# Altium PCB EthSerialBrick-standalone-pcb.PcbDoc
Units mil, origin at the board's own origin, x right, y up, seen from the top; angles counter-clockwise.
Board outline 3550 x 3775 mil, 4 copper layers (Top Layer, Internal Plane 1, Internal Plane 2, Bottom Layer); 57 components, 52 nets, 310 pads, 15 vias.
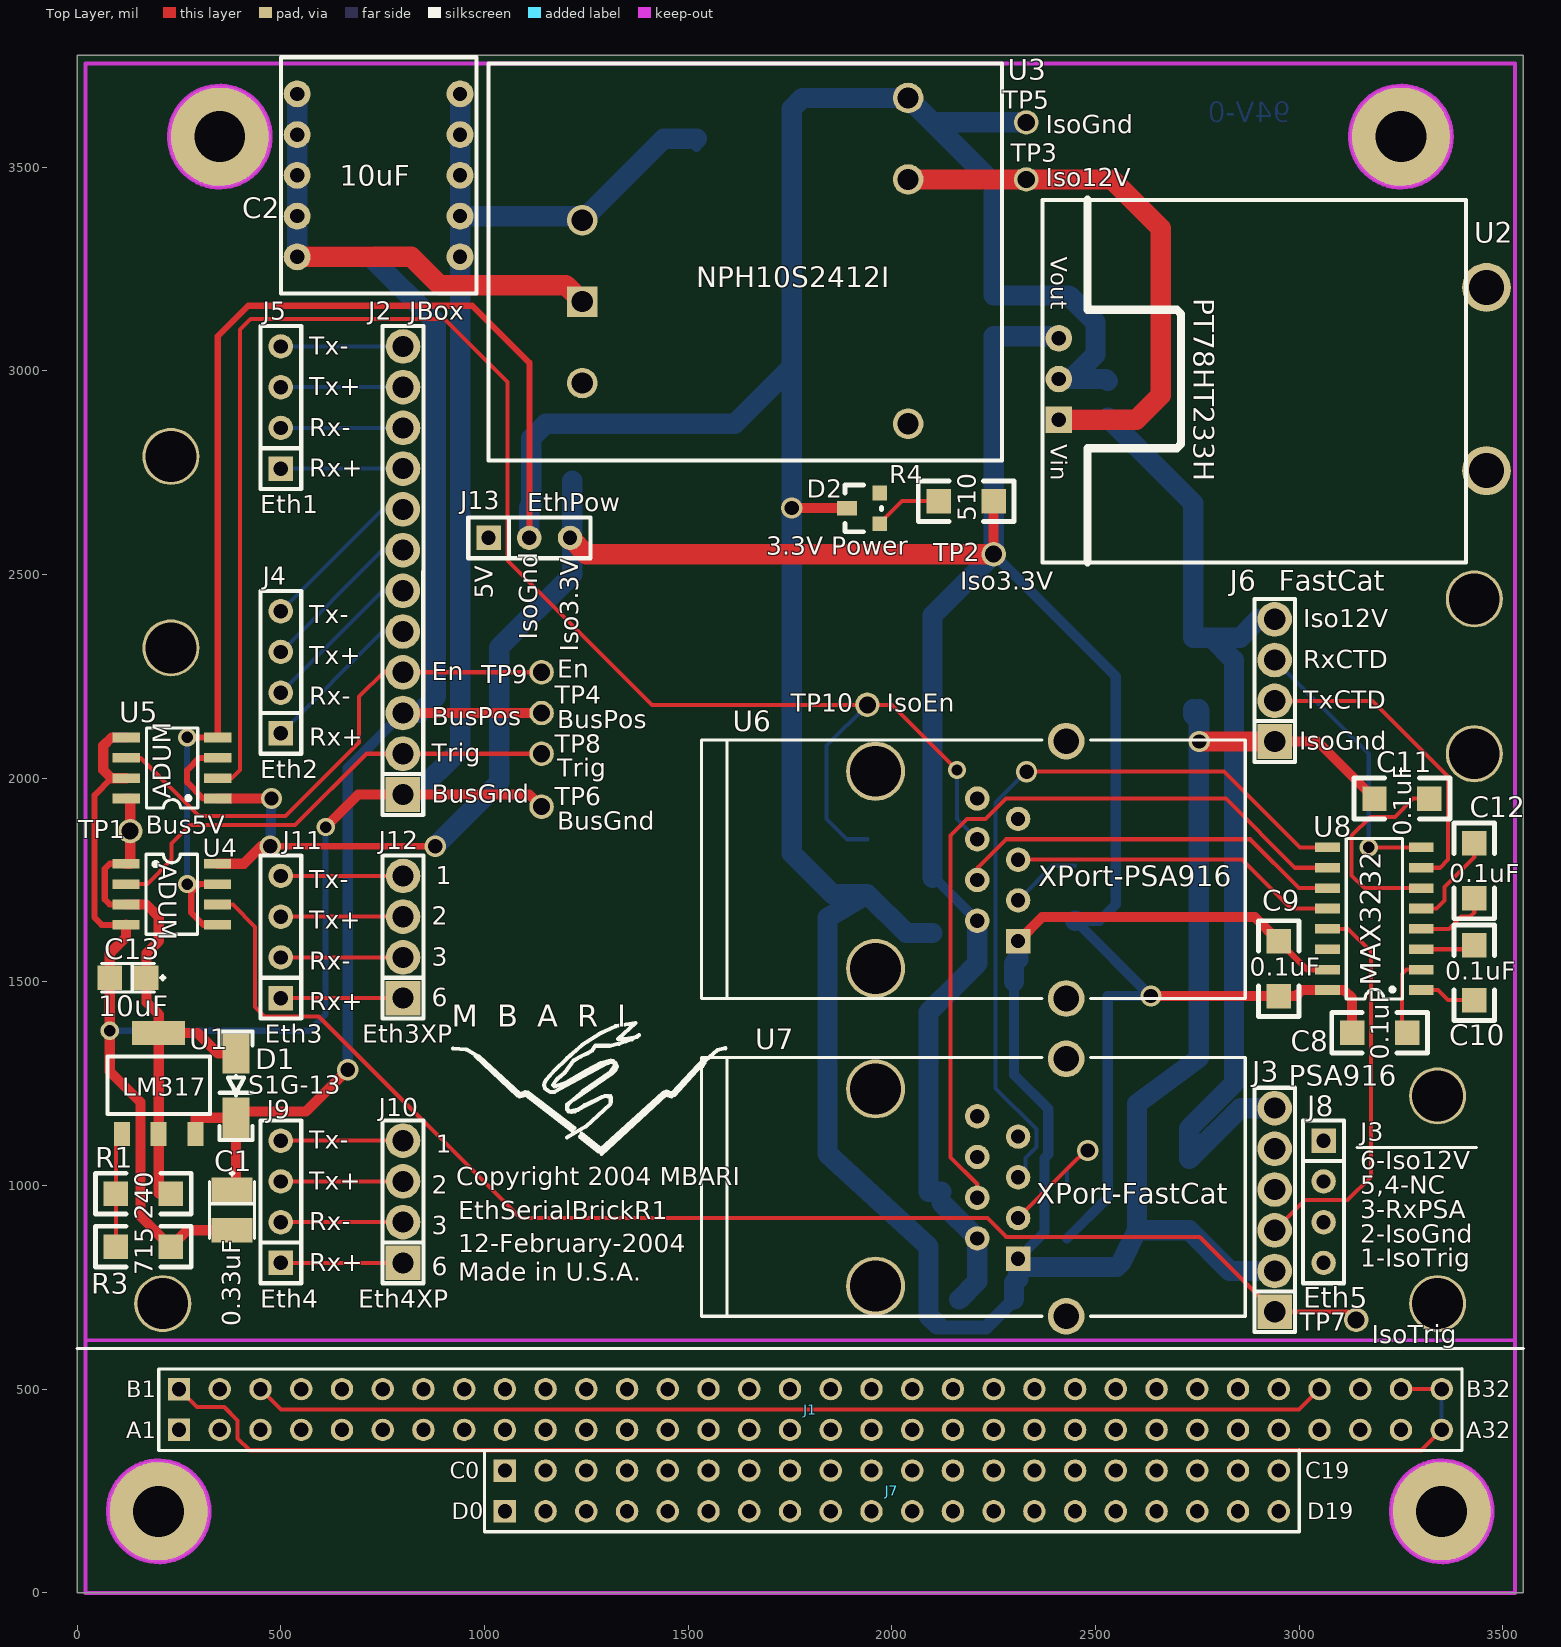
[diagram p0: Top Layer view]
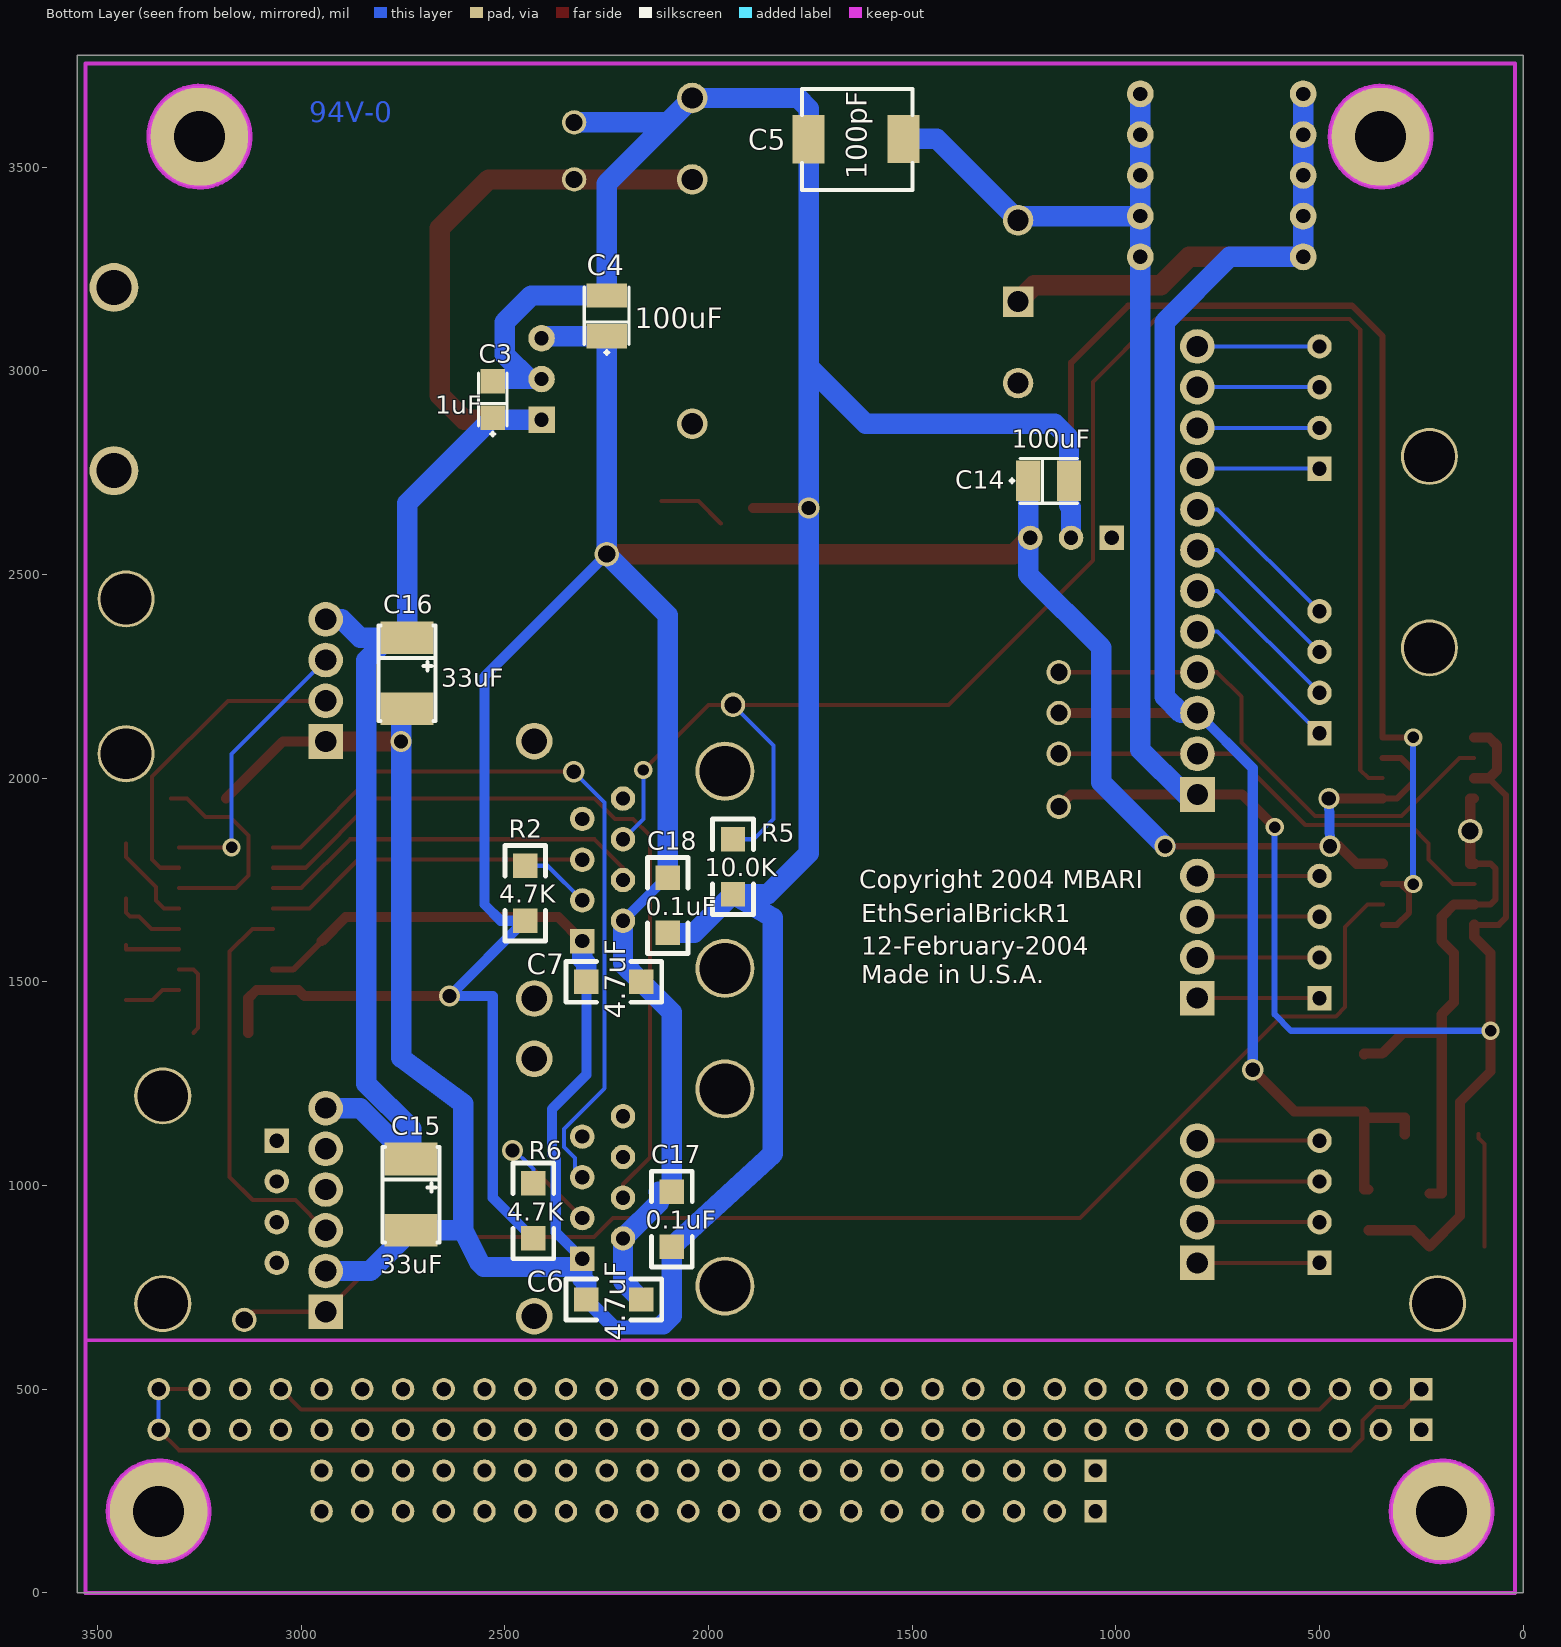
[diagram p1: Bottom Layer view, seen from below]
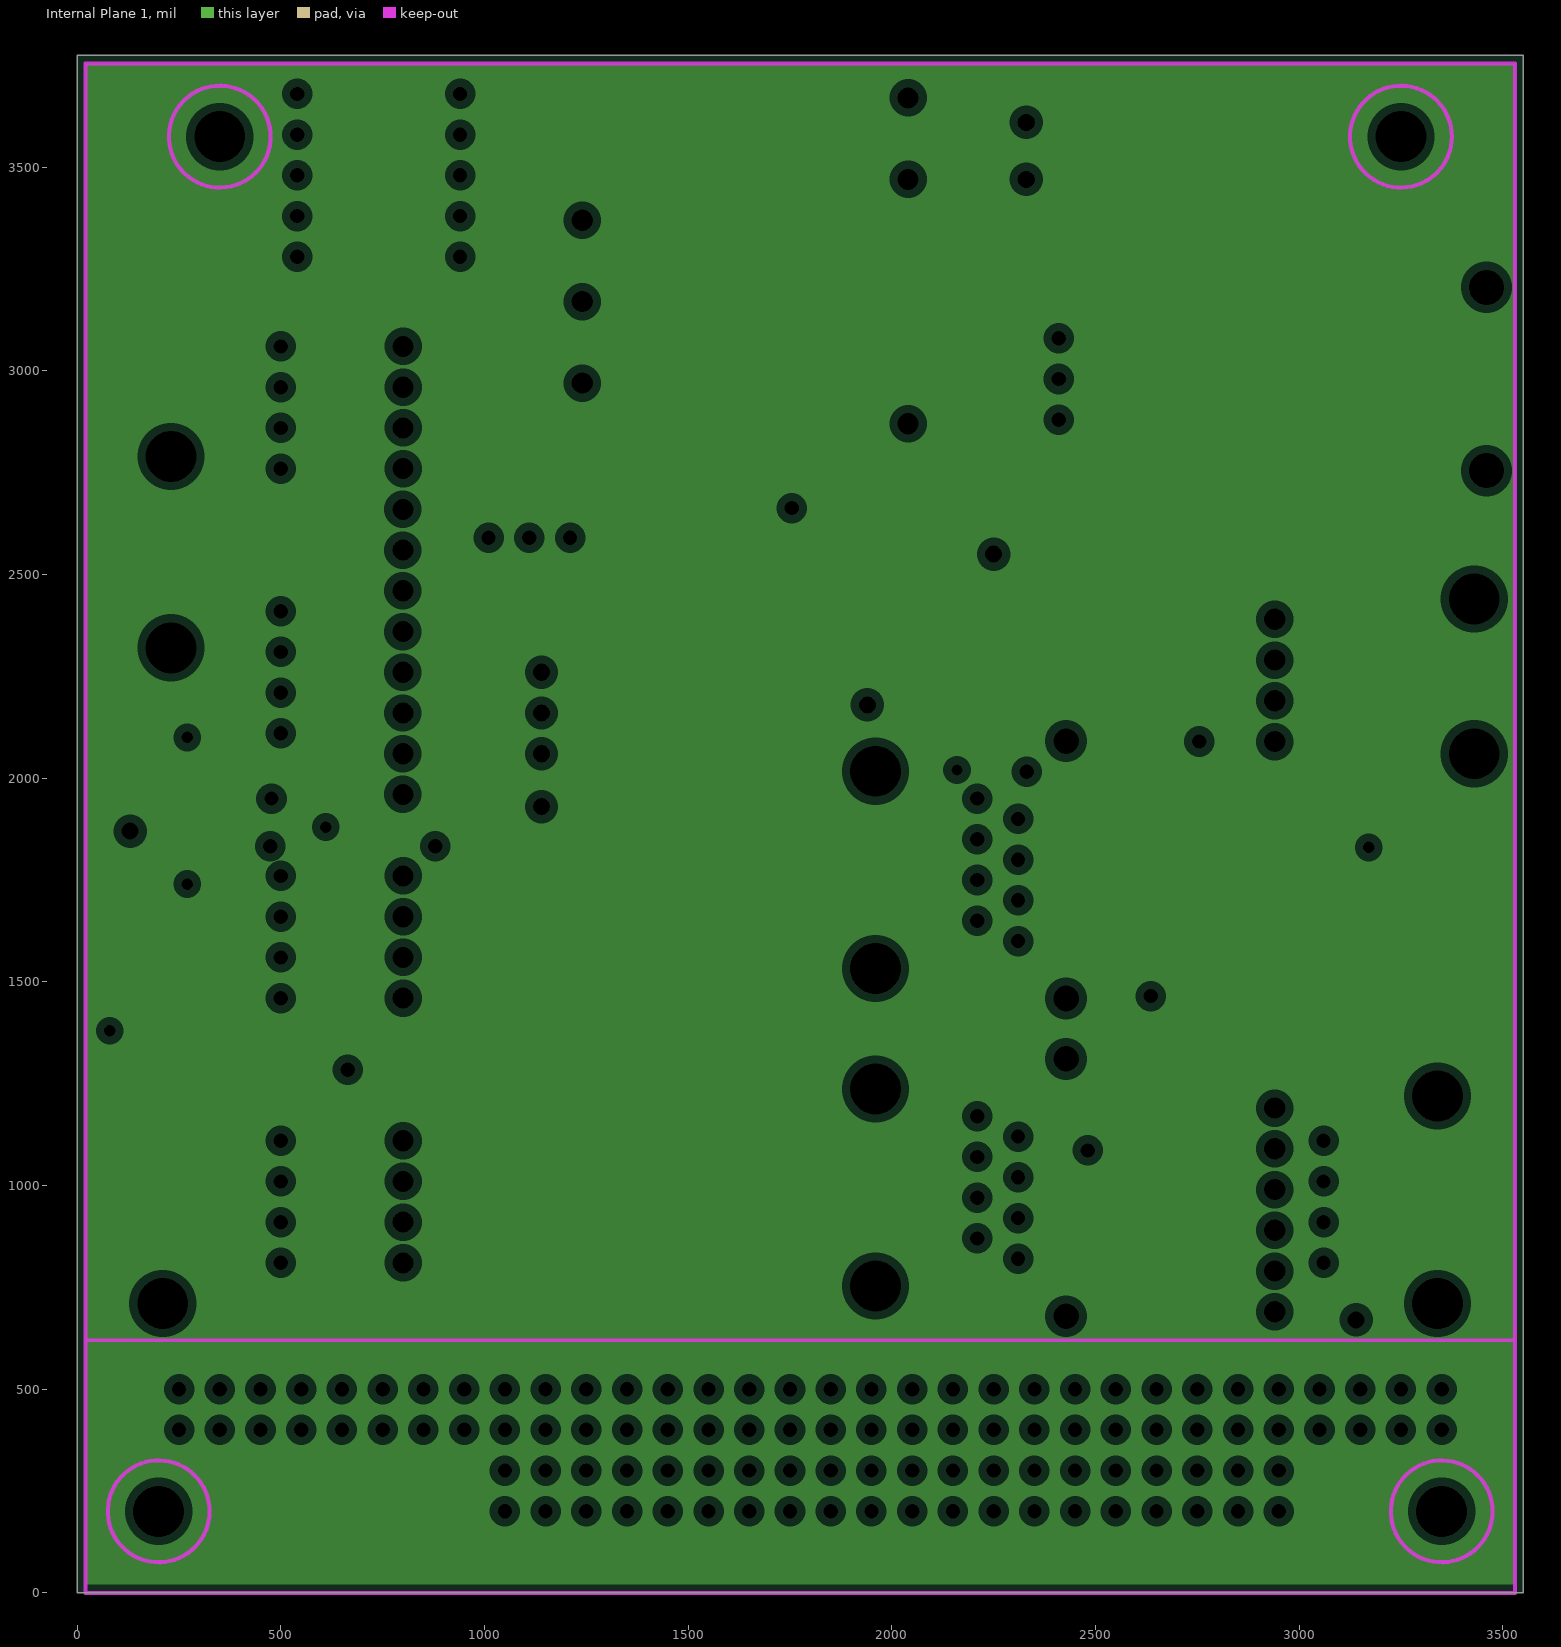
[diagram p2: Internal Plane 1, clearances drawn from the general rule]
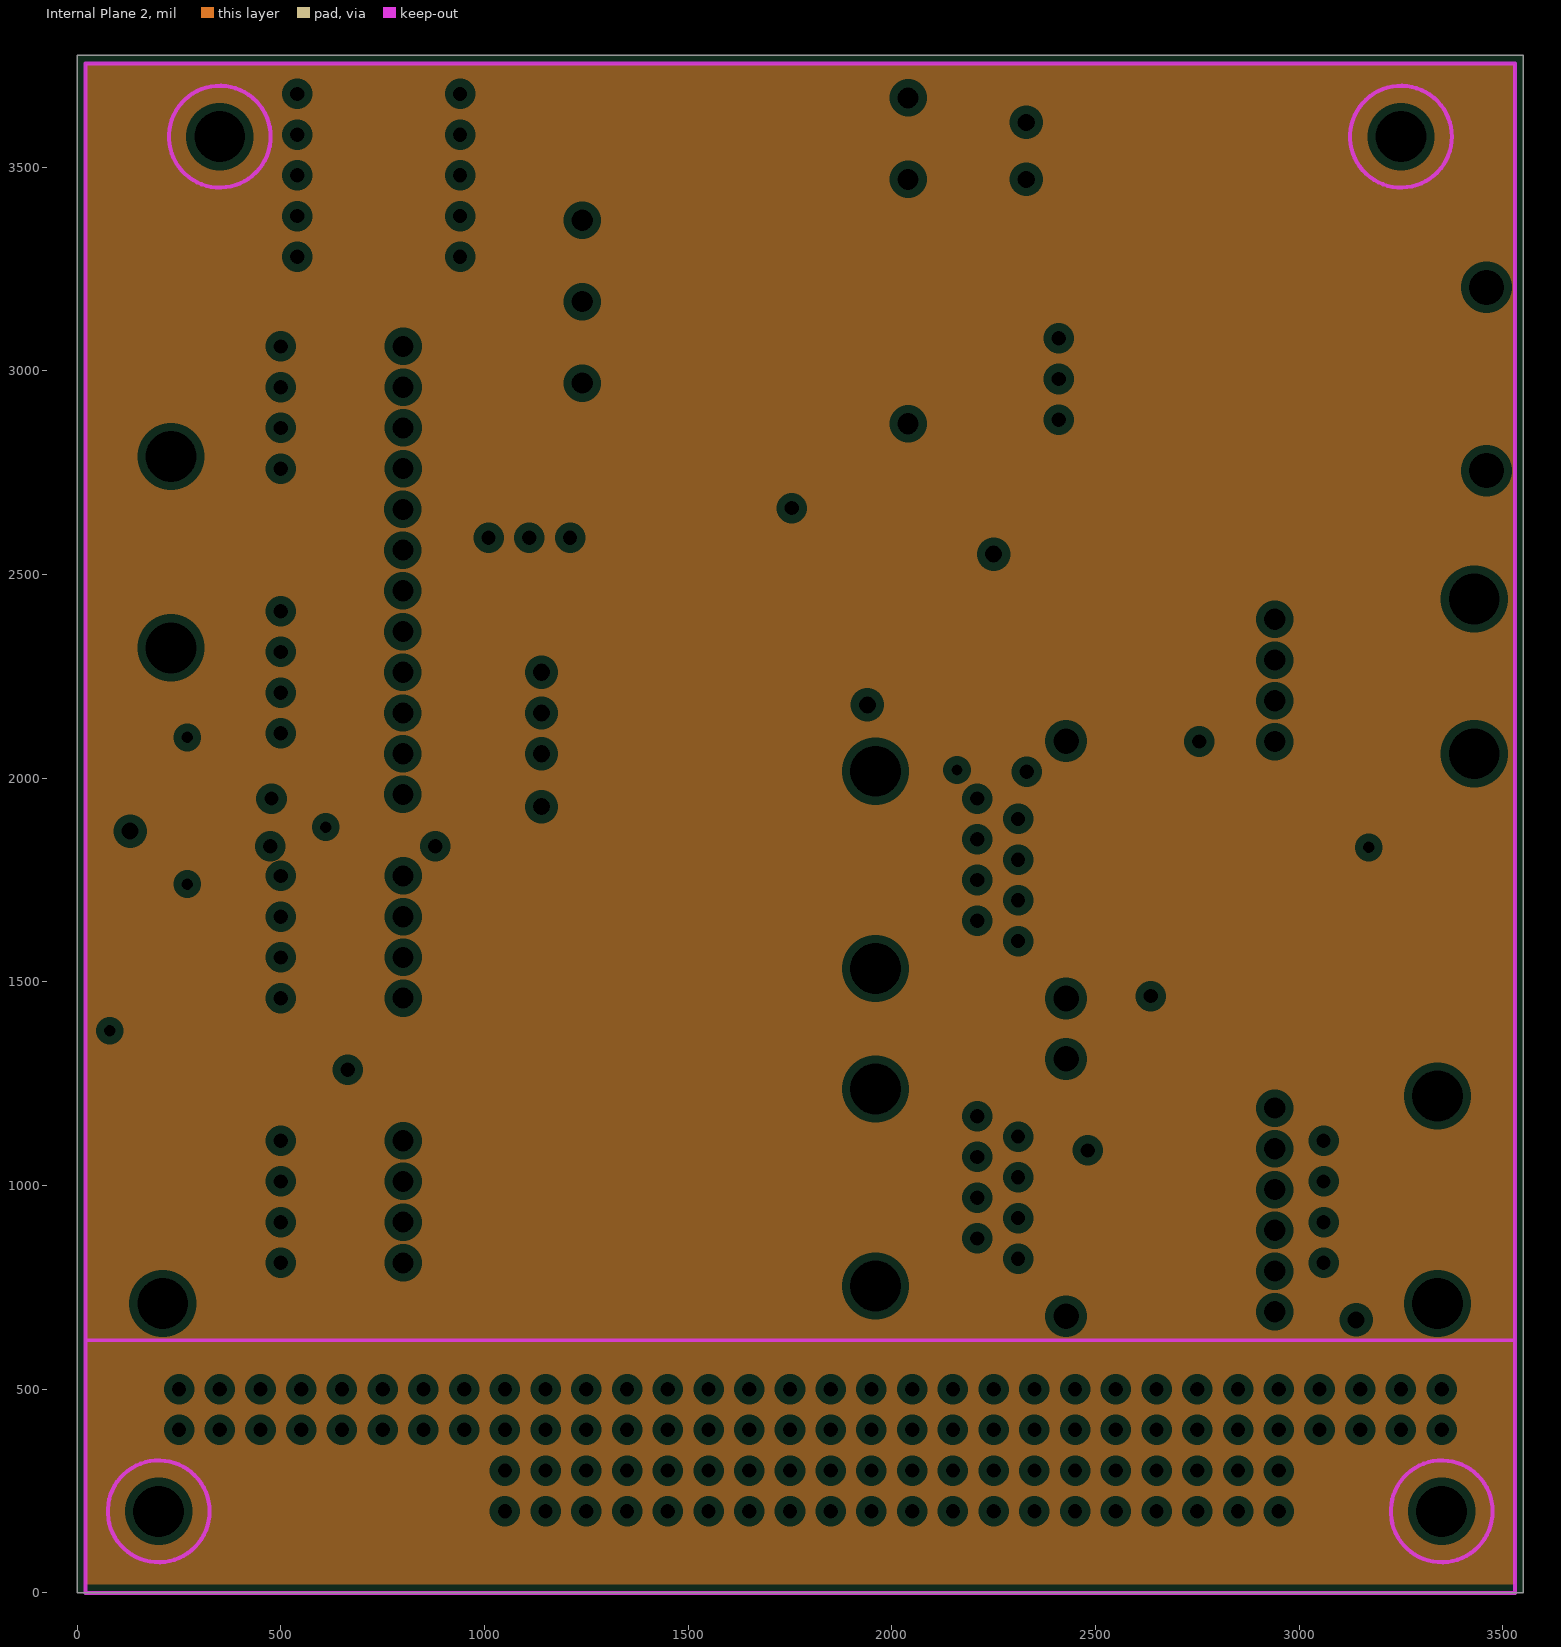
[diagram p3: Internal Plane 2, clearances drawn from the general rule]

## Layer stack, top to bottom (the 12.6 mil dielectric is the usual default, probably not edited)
Top Layer: signal copper 1.4
Dielectric: dielectric 12.6, FR-4, Dk 4.8
Internal Plane 1: plane copper 1.4
Dielectric: dielectric 12.6, FR-4, Dk 4.8
Internal Plane 2: plane copper 1.4
Dielectric: dielectric 12.6, FR-4, Dk 4.8
Bottom Layer: signal copper 1.4

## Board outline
0,0 0,3775 3550,3775 3550,0

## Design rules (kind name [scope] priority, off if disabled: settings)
Clearance Clearance_poly [InPolygon] p1: gap=16 // poly
Clearance [All] p2: gap=10
ComponentClearance [All] p1 off: gap=10 collisioncheckmode=0
FanoutControl Fanout_Small [(CompPinCount < 5)] p1: bgadir=Out bgaviamode=Centered fanoutstyle=Auto fanoutdirection=OutThenIn viagrid=1 // Fanout_Small (Default Rule)
FanoutControl Fanout_Default [All] p2: bgadir=Out bgaviamode=Centered fanoutstyle=Auto fanoutdirection=Alternating viagrid=1 // Fanout_Default (Default Rule)
FanoutControl Fanout_BGA [IsBGA] p4: bgadir=Out bgaviamode=Centered fanoutstyle=Auto fanoutdirection=Alternating viagrid=1 // Fanout_BGA (Default Rule)
FanoutControl Fanout_LCC [IsLCC] p5: bgadir=Out bgaviamode=Centered fanoutstyle=Auto fanoutdirection=Alternating viagrid=1 // Fanout_LCC (Default Rule)
HoleSize [All] p1: absolutevalues=TRUE maxlimit=152 minlimit=1 maxpercent=80.000 minpercent=20.000
MinimumAnnularRing [All] p1: minimumring=7.5
PlaneClearance [All] p1: clearance=20
PlaneConnect [All] p1: planeconnectstyle=Relief reliefexpansion=20 reliefentries=4 reliefconductorwidth=10 reliefairgap=10
PolygonConnect [All] p1: connectstyle=Relief reliefconductorwidth=10 reliefentries=4 polygonreliefangle="90 Angle"
RoutingLayers [All] p1: top layer=Horizontal bottom layer=Vertical
RoutingVias [All] p1: holewidth=28 width=45 viastyle="Through Hole" minholewidth=28 minwidth=43 maxholewidth=86 maxwidth=101
SolderMaskExpansion [All] p1: expansion=4
TestPointUsage [All] p1: valid=0 allowmultiple=FALSE
Testpoint [All] p1: side=15 testpointundercomponent=TRUE minsize=40 maxsize=100 preferedsize=60 minholesize=0 maxholesize=40 preferedholesize=32 testpointgrid=1 style=1023 order=1234567890
Width Width_power [InNetClass('Power')] p1: maxlimit=250 minlimit=10 preferedwidth=10 toplayer_prefwidth=25 bottomlayer_prefwidth=50 minimp=50.000000 maximp=50.000000 favimp=50.000000 // power width rule
Width [All] p2: maxlimit=250 minlimit=8 preferedwidth=12 toplayer_prefwidth=10 bottomlayer_prefwidth=10 minimp=50.000000 maximp=50.000000 favimp=50.000000
9 further rules are at their usual default settings.

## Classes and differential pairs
net class Power: BUS5V BUSGND BUSPOS ISO3.3V ISO12V ISOGND

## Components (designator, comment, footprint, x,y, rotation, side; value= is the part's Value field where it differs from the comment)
C1 "0.33uF" 3528POL 380,990 r270 top (schematic designator C13)
C2 "10uF" CAPSTICK-CS4-5 540,3280 r90 top
C3 "1uF" 3216POL 2530,2885 r90 bottom
C4 "100uF" 3528POL 2250,3085 r90 bottom
C5 "100pF" ECK 1514.92,3550 r0 bottom (schematic designator C11)
C6 "4.7uF" 1206 2165,720 r0 bottom (schematic designator C12)
C7 "4.7uF" 1206 2165,1500 r0 bottom (schematic designator C14)
C8 "0.1uF" 1206 3265,1375 r180 top (schematic designator C6)
C9 "0.1uF" 1206 2950,1465 r90 top (schematic designator C7)
C10 "0.1uF" 1206 3430,1455 r90 top (schematic designator C8)
C11 "0.1uF" 1206 3185,1950 r0 top (schematic designator C9)
C12 "0.1uF" 1206 3430,1705 r90 top (schematic designator C10)
C13 "10uF" 3216POL 170,1510 r180 top (schematic designator R4)
C14 "100uF" 3528POL 1215,2730 r180 bottom
C15 "33uF" 6032POL 2730,1065 r270 bottom
C16 "33uF" 6032POL 2740,2345 r270 bottom
C17 "0.1uF" 1206 2090,985 r270 bottom
C18 "0.1uF" 1206 2100,1755 r270 bottom
D1 "S1G-13" SMA 390,1245 r270 top (schematic designator D2)
D2 "3.3V Power" SOT-23 1970,2700 r90 top
J1 "PC104-AB" PC104-AB 250,400 r0 top locked (schematic designator J2)
J2 "JBox" SIP12 800,1960 r90 top (schematic designator J10)
J3 "PSA916" SIP6 2940,690 r90 top (schematic designator J11)
J4 "Eth2" SIP4#1 500,2110 r90 top locked (schematic designator J6)
J5 "Eth1" SIP4#1 500,2760 r90 top locked
J6 "FastCat" SIP4#2 2940,2090 r90 top (schematic designator J12)
J7 "PC104-CD" PC104-CD 1050,200 r0 top locked (schematic designator J3)
J8 "Eth5" SIP4#1 3060,1110 r270 top locked (schematic designator J9)
J9 "Eth4" SIP4#1 500,810 r90 top locked (schematic designator J8)
J10 "Eth4XP" SIP4#2 800,810 r90 top (schematic designator J13)
J11 "Eth3" SIP4#1 500,1460 r90 top locked (schematic designator J7)
J12 "Eth3XP" SIP4#2 800,1460 r90 top (schematic designator J14)
J13 "EthPow" SIP3 1010,2590 r0 top locked
R1 "240" 1206 230,980 r180 top (schematic designator R2)
R2 "4.7K" 1206 2450,1785 r270 bottom
R3 "715" 1206 230,850 r180 top
R4 "510" 1206 2250,2680 r180 top
R5 "10.0K" 1206 1940,1715 r90 bottom
R6 "4.7K" 1206 2430,1005 r270 bottom
TP1 "Bus5V" TP-PAD-35 130,1870 r0 top
TP2 "Iso3.3V" TP-PAD-35 2250,2550 r0 top
TP3 "Iso12V" TP-PAD-35 2330,3470 r0 top
TP4 "BusPos" TP-PAD-35 1140,2160 r0 top
TP5 "IsoGnd" TP-PAD-35 2330,3610 r0 top
TP6 "BusGnd" TP-PAD-35 1140,1930 r0 top
TP7 "IsoTrig" TP-PAD-35 3140,670 r90 top
TP8 "Trig" TP-PAD-35 1140,2060 r0 top
TP9 "En" TP-PAD-35 1140,2260 r90 top
TP10 "IsoEn" TP-PAD-35 1940,2180 r270 top
U1 "LM317EMP" SOT-223 200,1250 r0 top
U2 "PT78HT233H" PT78ST-HORIZ 2410,2980 r270 top (schematic designator U4)
U3 "NPH10S2412I" NPH10S 1240,3170 r180 top (schematic designator U9)
U4 "ADUM1100AR" SO-G8/D5 120,1790 r270 top (schematic designator U5)
U5 "ADUM1100AR" SO-G8/D5 345,1950 r90 top (schematic designator U6)
U6 "XPort-PSA916" XPORT 2310,1600 r0 top (schematic designator U3)
U7 "XPort-FastCat" XPORT 2310,820 r0 top
U8 "MAX3232" SOIC-16-0.15W 3300,1480 r90 top (schematic designator U2)

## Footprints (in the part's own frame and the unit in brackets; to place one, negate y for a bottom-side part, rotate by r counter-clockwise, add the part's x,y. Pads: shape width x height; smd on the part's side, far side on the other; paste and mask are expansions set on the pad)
1206 [mil]
  rect 60x60 smd: 1(0,0) 2(135,0)
  silkscreen extent -50,-50 185,50
3216POL [mil] "Polarized Cap EIA-3216-18, similiar to1206 footprint"
  rect 60x60 smd: 1(0,0) 2(90,0)
  silkscreen extent -45,-35 110,35
3528POL [mil] "Polarized chip capacitor EIA 3528-21"
  rect 60x100 smd: 1(0,0) 2(100,0)
  silkscreen extent -45,-55 120,55
6032POL [mil] "Polarized chip cap EIA 6032-28"
  rect 80x130 smd: 1(0,0) 2(175,0)
  silkscreen extent -30,-70 205,70
CAPSTICK-CS4-5 [mil]
  round 66 hole 35: 1(0,0) 1(100,0) 1(200,0) 1(300,0) 1(400,0) 2(0,-400) 2(100,-400) 2(200,-400) 2(300,-400) 2(400,-400)
  silkscreen extent -90,-440 490,40
ECK [mm]
  rect 2x3 smd: 1(0.15,-0.5) 2(6.075,-0.475)
  silkscreen extent -0.4,-3.6 6.5,2.7
NPH10S [mil]
  rect 75x75 hole 52: 1(0,0)
  round 75 hole 52: 2(0,-200) 3(-800,-500) 4(-800,-300) 5(0,200) 6(-800,300)
  silkscreen extent -1030,-585 230,390
PC104-AB [mil] "PC/104 A&B rails"
  rect 55x55 hole 35: A1(0,0) B1(0,100)
  round 55 hole 35: A2(100,0) A3(200,0) A4(300,0) A5(400,0) A6(500,0) A7(600,0) A8(700,0) A9(800,0) A10(900,0) A11(1000,0) A12(1100,0) A13(1200,0) A14(1300,0) A15(1400,0) A16(1500,0) A17(1600,0) A18(1700,0) A19(1800,0) A20(1900,0) A21(2000,0) A22(2100,0) A23(2200,0) A24(2300,0) A25(2400,0) A26(2500,0) A27(2600,0) A28(2700,0) A29(2800,0) A30(2900,0) A31(3000,0) A32(3100,0) B2(100,100) B3(200,100) B4(300,100) B5(400,100) B6(500,100) B7(600,100) B8(700,100) B9(800,100) B10(900,100) B11(1000,100) B12(1100,100) B13(1200,100) B14(1300,100) B15(1400,100) B16(1500,100) B17(1600,100) B18(1700,100) B19(1800,100) B20(1900,100) B21(2000,100) B22(2100,100) B23(2200,100) B24(2300,100) B25(2400,100) B26(2500,100) B27(2600,100) B28(2700,100) B29(2800,100) B30(2900,100) B31(3000,100) B32(3100,100)
  silkscreen extent -50,-50 3150,150
PC104-CD [mil] "PC/104 C&D rails"
  rect 55x55 hole 35: C0(0,100) D0(0,0)
  round 55 hole 35: C1(100,100) C2(200,100) C3(300,100) C4(400,100) C5(500,100) C6(600,100) C7(700,100) C8(800,100) C9(900,100) C10(1000,100) C11(1100,100) C12(1200,100) C13(1300,100) C14(1400,100) C15(1500,100) C16(1600,100) C17(1700,100) C18(1800,100) C19(1900,100) D1(100,0) D2(200,0) D3(300,0) D4(400,0) D5(500,0) D6(600,0) D7(700,0) D8(800,0) D9(900,0) D10(1000,0) D11(1100,0) D12(1200,0) D13(1300,0) D14(1400,0) D15(1500,0) D16(1600,0) D17(1700,0) D18(1800,0) D19(1900,0)
  silkscreen extent -50,-50 1950,150
PT78ST-HORIZ [mil]
  round 120 hole 86: 0(-225,1050) 0(225,1050)
  rect 65x65 hole 35: 1(100,0)
  round 65 hole 35: 2(0,0) 3(-100,0)
  silkscreen extent -440,-40 450,1000
SIP3 [mil]
  rect 60x60 hole 35: 1(0,0)
  round 60 hole 35: 2(100,0) 3(200,0)
  silkscreen extent -50,-50 250,50
SIP4#1 [mil]
  rect 60x60 hole 35: 1(0,0)
  round 60 hole 35: 2(100,0) 3(200,0) 4(300,0)
  silkscreen extent -50,-50 350,50
SIP4#2 [mil]
  rect 85x85 hole 52: 1(0,0)
  round 85 hole 52: 2(100,0) 3(200,0) 4(300,0)
  silkscreen extent -50,-50 350,50
SIP6 [mil]
  rect 85x85 hole 52: 1(0,0)
  round 85 hole 52: 2(100,0) 3(200,0) 4(300,0) 5(400,0) 6(500,0)
  silkscreen extent -50,-50 550,50
SIP12 [mil] "12 position SIP"
  rect 85x85 hole 52: 1(0,0.38)
  round 85 hole 52: 2(100,0.38) 3(200,0.38) 4(300,0.38) 5(400,0.38) 6(500,0.38) 7(600,0.38) 8(700,0.38) 9(800,0) 10(900,0) 11(1000,0) 12(1100,0)
  silkscreen extent -50,-50 1150,50
SMA [mm] "SMA Diode"
  rect 2.5x1.7 smd: 1(-2,0) 2(2,0)
  silkscreen extent -3.38,-1.02 3.38,1.02
SO-G8/D5 [mm]
  rect 0.6x1.7 smd: 1(0,0) 2(1.27,0) 3(2.54,0) 4(3.81,0) 5(3.81,5.7) 6(2.54,5.7) 7(1.27,5.7) 8(0,5.7)
  silkscreen extent -0.59,1.25 4.41,4.45
SOIC-16-0.15W [mm] "SOIC-16 0.15\"Wide 1.27mm Pitch"
  rect 0.6x1.55 smd: 1(0,0) 2(1.27,0) 3(2.54,0) 4(3.81,0) 5(5.08,0) 6(6.35,0) 7(7.62,0) 8(8.89,0) 9(8.89,5.85) 10(7.62,5.85) 11(6.35,5.85) 12(5.08,5.85) 13(3.81,5.85) 14(2.54,5.85) 15(1.27,5.85) 16(0,5.85)
  silkscreen extent -0.55,1.18 9.44,4.67
SOT-23 [mil]
  rect 36x36 smd: 1(0,0) 2(-75,0)
  rect 36x50 smd: 3(-37,80)
  silkscreen extent -95,-5 20,85
SOT-223 [mm] "4 lead SMD NS:MP04A"
  rect 1x1.5 smd: 1(-2.3,-3.15) 2(0,-3.15) 3(2.3,-3.15)
  rect 3.3x1.5 smd: 4(0,3.15)
  silkscreen extent -3.2,-1.9 3.2,1.7
TP-PAD-35 [mil] "TestPoint 35mil"
  round 60 hole 42: 0(0,0)
XPORT [mil]
  round 145 hole 125: 0(-350,-67) 0(-350,417)
  rect 60x60 hole 35: 1(0,0)
  round 60 hole 35: 2(-100,50) 3(0,100) 4(-100,150) 5(0,200) 6(-100,250) 7(0,300) 8(-100,350)
  round 90 hole 63: 9(118,-141) 10(118,491)
  silkscreen extent -777,-141 558,494

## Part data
C1 C3 C4 C13 C14 C15 C16: library part "CAPACITOR POL", "Capacitor"
C2 C6 C7 C8 C9 C10 C11 C12 C17 C18: library part CAPACITOR, "Capacitor"
C5: library part Cap, "Capacitor"
D1: library part DIODE_S, "Diode"
D2: library part LED, "LED"
J1: "PC/104 A&B rails"
J2: library part CON12, "Connector 12 pin"
J3: library part CON6, "Connector"
J4 J5 J8 J9 J10 J11 J12: library part CON4, "Connector 4 pin"
J6: library part CON4, "Connector"
J7: "PC/104 C&D rails"
J13: library part CON3, "Connector"
R1 R2 R3 R4 R5 R6: library part RESISTOR, "Resistor"
TP1 TP2 TP3 TP4 TP5 TP6 TP7 TP8 TP9 TP10: library part "TP PIN", "Pad Pin for testpoints"
U1: library part LM317, "Regulator"
U2: library part PT78STXXX, "Power Trends Switching Reg"
U3: library part NPH10S, "DC->DC Isol Converter 10W"
U4 U5: "Digital Isolator"
U6 U7: library part XPORT, "Serial to Ethernet Converter"
U8: library part MAX232, "MAX232 Communications Chip"

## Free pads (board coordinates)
  round 250 hole 125: 0(200,200) 0(350,3575) 0(3250,3575) 0(3350,200)
  round 140 hole 125: 0(210,710) 0(230,2320) 0(230,2790) 0(3340,710) 0(3340,1220) 0(3430,2060) 0(3430,2440)

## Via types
v1: diameter 52, hole 35, Top Layer to Bottom Layer, 9 vias
v2: diameter 45, hole 28, Top Layer to Bottom Layer, 6 vias

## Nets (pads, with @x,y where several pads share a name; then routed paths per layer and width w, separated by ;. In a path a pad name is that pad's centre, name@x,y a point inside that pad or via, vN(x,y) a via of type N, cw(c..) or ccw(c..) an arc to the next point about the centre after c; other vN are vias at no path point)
104+5V: J1.B3 J1.B29 | length 2641.4
  Top Layer w10: J1.B3 500,450 3000,450 J1.B29
104GND: J1.A32 J1.B1 J1.B31 J1.B32 | length 3408.6
  Top Layer w10: J1.B1 294,456 361,456 394,423 394,379 423,350 3300,350 J1.A32 ; J1.B31 J1.B32
  Bottom Layer w10: J1.A32 J1.B32
BUS5V: C13.1 D1.1 R1.1 TP1.0 U1.2 U1.4 U4.1 U4.3 U5.8 | length 1409.6
  Top Layer w15: U4.3 80,1690 67.5,1702.5 67.5,1777.5 80,1790 U4.1
  Top Layer w25: U4.3 170,1690 200,1660 200,1600 170,1570 C13.1 170,1450 200,1420 U1.4 ; U4.1 130,1790 TP1.0 130,1950 U5.8 ; R1.1 200,980 U1.2 U1.4 ; D1.1@390,1322 D1.1 346.26,1323.74 295.98,1374.02 U1.4
BUSGND: C1.2 C2.2 C5.1 C13.2 J2.1 R3.1 TP6.0 U3.2 U4.4 U5.5 U5.7 | length 5771.5
  Top Layer w15: U4.4 60,1640 42.5,1657.5 42.5,1958.5 84,2000 U5.7
  Top Layer w25: U4.4 120,1610 80,1570 C13.2 80,1280 155,1205 155,925 R3.1 270,890 299,890 C1.2 ; U5.7 84,2000 64,2020 64,2080 84,2100 U5.5 ; v2(610,1880) 690,1960 J2.1 1110,1960 TP6.0
  Bottom Layer w15: v2(80,1380) 570,1380 610,1420 v2(610,1880)
  Bottom Layer w25: C5.1@1520.83,3550 C5.1
  Bottom Layer w50: J2.1 830,1960 940,2070 940,3280 C2.2@940,3380 ; C2.2@940,3680 940,3580 940,3480 C2.2@940,3380 ; C5.1 1439.69,3569.69 U3.2 1230,3380 C2.2@940,3380
BUSPOS: C1.1 C2.1 D1.2 J2.3 TP4.0 U1.3 U3.1 | length 4499.3
  Top Layer w25: U1.3 290.55,1166.26 D1.2 ; C1.1 390,990 D1.2 ; v1(664,1284) 562,1182 390,1182 D1.2 ; J2.3 TP4.0
  Top Layer w50: C2.1@540,3280 820,3280 890,3210 1200,3210 U3.1
  Bottom Layer w25: v1(664,1284) 664,2024.38 J2.3
  Bottom Layer w50: C2.1@540,3680 540,3580 540,3480 540,3380 540,3280 720,3280 880,3120 880,2200 840,2160 J2.3
EN: J2.4 TP9.0 U5.6 | length 1290.5
  Top Layer w10: U5.6 156,2050 299,1907 511,1907 692,2088 692,2200 752,2260 J2.4 TP9.0
ISO3.3V: C4.1 C6.1 C7.1 C8.2 C9.1 C14.1 C17.1 C18.1 J13.3 R2.2 R4.1 R6.2 TP2.0 U2.3 U4.8 U5.1 U5.3 U6.2 U7.2 U8.16 | length 8722.1
  Top Layer w15: U5.1 310,1950 270,1990 270,2020 300,2050 U5.3 ; v1(474,1833) v1(879,1833)
  Top Layer w25: U4.8 409,1790 452,1833 v1(474,1833) ; U5.1 v1(477,1950) ; TP2.0 R4.1 ; v1(2636,1465) C9.1 2992,1465 3007,1480 U8.16 3110,1480 3130,1460 C8.2
  Top Layer w50: J13.3 1250,2550 TP2.0
  Bottom Layer w25: v1(474,1833) v1(477,1950) ; C18.1 2105,1755 U6.2 ; 2122,958 2122,985 ; TP2.0 2503,2297 2550,2250 2550,1690 2510,1650 R2.2 ; R6.2 2530,970 2530,1465 v1(2636,1465) R2.2@2451,1650
  Bottom Layer w50: v1(879,1833) 1036,1990 1036,2321 1215,2500 J13.3@1215,2590 ; J13.3 J13.3@1215,2590 ; C14.1 J13.3@1215,2590 ; C18.1 2100,2400 TP2.0 C4.1 2405,3085 U2.3 U2.3@2400,3080 ; 2122,958 U7.2 2210,765 C6.1 ; 2122,985 C17.1 2090,1425 C7.1 2210,1545 U6.2 ; R2.2 R2.2@2451,1650
ISO12V: C3.1 C15.1 C16.1 J3.6 J6.4 TP3.0 U2.1 U3.4 | length 3977.4
  Top Layer w50: U3.4 TP3.0 2540,3470 2660,3350 2660,2940 2600,2880 U2.1
  Bottom Layer w50: U2.1 2525,2880 C3.1 2740,2675 C16.1 ; J3.6 2855,1190 C15.1 2730,1140 2840,1250 2840,2290 2785,2345 C16.1 ; J6.4 2900,2390 2855,2345 C16.1
ISOEN: R5.2 TP10.0 U5.2 U6.6 | length 4263
  Top Layer w10: U5.2 380,2000 400,2020 400,3101 426,3127 902,3127 1056,2973 1056,2535 1411,2180 TP10.0 2000,2180 v2(2160,2020)
  Bottom Layer w10: R5.2 1890,1850 1840,1900 1840,2080 TP10.0 ; v2(2160,2020) 2160,1900 U6.6
ISOGND: C3.2 C4.2 C5.2 C6.2 C7.2 C9.2 C11.1 C14.2 C15.2 C16.2 C17.2 C18.2 D2.3 J3.2 J6.1 J13.2 R5.1 TP5.0 U2.2 U3.3 U4.5 U4.7 U5.4 U6.1 U7.1 U8.15 | length 14019.7
  Top Layer w15: v2(270,1740) U4.7 300,1740 280,1720 280,1670 310,1640 U4.5 ; v2(270,2100) U5.4 345,3085 420,3160 970,3160 1110,3020 J13.2 ; C9.2 3020,1530 U8.15
  Top Layer w25: v1@1754.09,2663 v1@1768,2663 ; v1(1754.09,2663.09) 1767.91,2663.09 v1@1768,2663 ; D2.3 1809,2663 v1@1768,2663 ; U6.1 2369,1659 2891,1659 C9.2 ; J6.1 3045,2090 C11.1
  Top Layer w50: v1(2755,2090) J6.1
  Bottom Layer w15: v2(270,1740) v2(270,2100)
  Bottom Layer w25: C7.2 2300,1272 2384,1188 2384,1076 2375,1067 2375,885 2345.5,855.5 U7.1
  Bottom Layer w35: 2111,659 2118.5,651.5 2231.5,651.5 C6.2
  Bottom Layer w50: J13.2 1110,2665 1115,2670 C14.2 1115,2835 1150,2870 1614.09,2870 1754.09,3010 ; C18.2 2035,1620 R5.1 ; 2111,659 2090,680 C17.2 1842,1078 1842,1657 R5.1 ; C6.2 2300,761 2310,771 U7.1 2330,800 2552,800 2563,811 2602,890 ; C7.2 2300,1545 2310,1555 U6.1 ; TP5.0 2100,3610 U3.3 ; U2.2 2525,2980 C3.2 ; U2.2@2440,2980 2500,3040 2500,3120 2435,3185 C4.2 2250,3460 U3.3 ; C16.2 2740,2155 C16.2@2755,2140 ; C16.2@2754,2170 2754,1416 2754,1313 2602,1201 2602,890 ; v1(2755,2090) C16.2@2755,2165 ; J3.2 2830,790 C15.2 2602,890 ; 1754.09,3010 C5.2 1754.09,3644.09 1780,3670 U3.3 ; 1754.09,3010 v1(1754.09,2663.09) 1754.09,1815.91 1855,1715 R5.1
ISOTRIG: J3.1 TP7.0 U4.6 | length 3333.5
  Top Layer w10: U4.6 382,1690 437,1635 437,1438 460,1415 593,1415 1088,920 2235,920 2281,874 2756,874 J3.1 3120,690 TP7.0
NetC8_1: C8.1 U8.2 | length 200.5
  Top Layer w10: C8.1 3253,1387 3253,1519 3264,1530 U8.2
NetC10_1: C10.1 U8.1 | length 140.4
  Top Layer w10: U8.1 3340.51,1480 3365.51,1455 C10.1
NetC10_2: C10.2 U8.3 | length 140
  Top Layer w10: U8.3 3430,1580 C10.2
NetC11_2: C11.2 U8.6 | length 510.5
  Top Layer w10: U8.6 3160,1730 3129,1761 3129,1839 3129,1859 3175,1905 3195,1905 3235,1905 3280,1950 C11.2
NetC12_1: C12.1 U8.4 | length 181.6
  Top Layer w10: U8.4 3368,1630 3398,1660 3420,1660 3430,1670 C12.1
NetC12_2: 
NetC12_2: C12.2 U8.5 | length 235.5
  Top Layer w10: U8.5 3337,1680 3357,1700 3357,1733 3430,1806 C12.2
NetD2_2: D2.2 R4.2 | length 167.8
  Top Layer w10: D2.2 2025,2680 R4.2
NetJ2_5: J2.5 J4.1 | length 403.2
  Bottom Layer w10: J4.1 750,2360 J2.5
NetJ2_6: J2.6 J4.2 | length 403.2
  Bottom Layer w10: J4.2 750,2460 J2.6
NetJ2_7: J2.7 J4.3 | length 403.2
  Bottom Layer w10: J4.3 750,2560 J2.7
NetJ2_8: J2.8 J4.4 | length 403.2
  Bottom Layer w10: J4.4 750,2660 J2.8
NetJ2_9: J2.9 J5.1 | length 300
  Bottom Layer w10: J5.1 J2.9
NetJ2_10: J2.10 J5.2 | length 300
  Bottom Layer w10: J5.2 J2.10
NetJ2_11: J2.11 J5.3 | length 300
  Bottom Layer w10: J5.3 J2.11
NetJ2_12: J2.12 J5.4 | length 300
  Bottom Layer w10: J5.4 J2.12
NetJ9_1: J9.1 J10.1 | length 300
  Top Layer w10: J9.1 J10.1
NetJ9_2: J9.2 J10.2 | length 300
  Top Layer w10: J9.2 J10.2
NetJ9_3: J9.3 J10.3 | length 300
  Top Layer w10: J9.3 J10.3
NetJ9_4: J9.4 J10.4 | length 300
  Top Layer w10: J9.4 J10.4
NetJ11_1: J11.1 J12.1 | length 300
  Top Layer w10: J11.1 J12.1
NetJ11_2: 
NetJ11_2: J11.2 J12.2 | length 300
  Top Layer w10: J11.2 J12.2
NetJ11_3: 
NetJ11_3: J11.3 J12.3 | length 300
  Top Layer w10: J11.3 J12.3
NetJ11_4: J11.4 J12.4 | length 300
  Top Layer w10: J11.4 J12.4
NetJ12_1: 
NetJ12_2: 
NetJ12_3: 
NetR1_2: R1.2 R3.2 U1.1 | length 282
  Top Layer w10: R3.2 R1.2 95,1101.55 109.45,1116 U1.1
NetR2_1: R2.1 U6.3 | length 175.2
  Bottom Layer w10: U6.3 2395,1785 R2.1
NetR6_1: R6.1 U7.3 | length 342.3
  Top Layer w10: U7.3 2456,1066 v1(2481,1086)
  Bottom Layer w10: R6.1 2430,1040 2456,1066 v1(2481,1086)
NetU6_4: U6.4 U8.11 | length 968.4
  Top Layer w10: U6.4 2210,1780 2280,1850 2880,1850 3000,1730 U8.11
NetU6_5: U6.5 U8.12 | length 809.4
  Top Layer w10: U6.5 2860,1800 2980,1680 U8.12
NetU7_4: U7.4 U8.10 | length 1950.1
  Top Layer w10: U7.4 2210,1003 2144,1069 2144,1859 2185,1900 2230,1900 2280,1950 2820,1950 2990,1780 U8.10
NetU7_5: U7.5 U8.9 | length 1913.8
  Top Layer w10: v1(2331,2016) 2816,2016 3002,1830 U8.9
  Bottom Layer w10: U7.5 2328,1020 2328,1068 2355,1095 2355,1138.64 2255,1238.64 2255,1940 v1(2331,2016)
RX1: J3.3 U8.13 | length 972.8
  Top Layer w10: J3.3 3014,964 3119,964 3176,1021 3176,1574 3120,1630 U8.13
RX2: J6.3 U8.8 | length 683.7
  Top Layer w10: v2@3172,1830 U8.8
  Bottom Layer w10: J6.3 3171,2059 v2(3171,1830)
TRIG: J2.2 TP8.0 U4.2 | length 1176
  Top Layer w10: U4.2 172,1740 232,1800 232,1840 277,1885 535,1885 710,2060 J2.2 TP8.0
TX1: U8.14
TX2: J6.2 U8.7 | length 781.2
  Top Layer w10: J6.2 3179.79,2190 3366,2003.79 3366,1800 3346,1780 U8.7
pads on no net: D2.1 J1.A1 J1.A2 J1.A3 J1.A4 J1.A5 J1.A6 J1.A7 J1.A8 J1.A9 J1.A10 J1.A11 J1.A12 J1.A13 J1.A14 J1.A15 J1.A16 J1.A17 J1.A18 J1.A19 J1.A20 J1.A21 J1.A22 J1.A23 J1.A24 J1.A25 J1.A26 J1.A27 J1.A28 J1.A29 J1.A30 J1.A31 J1.B2 J1.B4 J1.B5 J1.B6 J1.B7 J1.B8 J1.B9 J1.B10 J1.B11 J1.B12 J1.B13 J1.B14 J1.B15 J1.B16 J1.B17 J1.B18 J1.B19 J1.B20 J1.B21 J1.B22 J1.B23 J1.B24 J1.B25 J1.B26 J1.B27 J1.B28 J1.B30 J3.4 J3.5 J7.C0 J7.C1 J7.C2 J7.C3 J7.C4 J7.C5 J7.C6 J7.C7 J7.C8 J7.C9 J7.C10 J7.C11 J7.C12 J7.C13 J7.C14 J7.C15 J7.C16 J7.C17 J7.C18 J7.C19 J7.D0 J7.D1 J7.D2 J7.D3 J7.D4 J7.D5 J7.D6 J7.D7 J7.D8 J7.D9 J7.D10 J7.D11 J7.D12 J7.D13 J7.D14 J7.D15 J7.D16 J7.D17 J7.D18 J7.D19 J8.1 J8.2 J8.3 J8.4 J13.1 U2.0 U3.5 U3.6 U6.0 U6.7 U6.8 U6.9 U6.10 U7.0 U7.6 U7.7 U7.8 U7.9 U7.10

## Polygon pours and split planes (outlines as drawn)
no net on Internal Plane 1 (split plane): 20.01,20.01 20.01,3754.98 3529.98,3754.98 3529.98,20.01
no net on Internal Plane 2 (split plane): 20.01,20.01 20.01,3754.98 3529.98,3754.98 3529.98,20.01

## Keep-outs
Keep-Out Layer:
  circle w10: c200,200 r125
  circle w10: c350,3575 r125
  circle w10: c3250,3575 r125
  circle w10: c3350,200 r125
  lines w8: 20,620 3530,620
  lines w10: 20,0 3530,0 3530,3755 20,3755 20,0
  text ".GKO" at 15240,-540 h90

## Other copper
Top Layer:
  text ".GTL" at 15240,-540 h90
Bottom Layer:
  text "94V-0" at 2980,3610 h50
  text ".GBL" at 15240,-540 h90

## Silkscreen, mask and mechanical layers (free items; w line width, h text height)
Top Overlay:
  lines w8: 0,600 3550,600 ; 3142,1092.99 3435.01,1092.99
  lines w10: 923,1336 955,1334 986,1316 1087,1225 1100,1229 1107,1228 1221,1141 ; 978,1318 1081,1221 ; 1086,1218 1101,1222 1216,1134 ; 1203,1118 1249,1145 1308,1199 1311,1206 1311,1216 1309,1219 1303,1220 1296,1220 ; 1234,1120 1281,1083 ; 1238,1127 1286,1089 1438,1227 1447,1231 1461,1226 1540,1312 1543,1307 1572,1333 1592,1337 ; 1310,1205 1310,1213 1308,1217 1303,1219 1296,1220 ; 1444,1223 1459,1218 ; 1466,1222 1531,1295 ; 1534,1292 1540,1301 ; 1296,1220 1289,1217 1246,1197 1229,1186 1206,1182 1202,1187 1203,1199 1241,1231 1309,1278 1320,1294 1316,1305 1310,1307 1286,1301 1250,1281 1202,1253 1172,1243 1168,1247 1179,1262 1197,1277 1219,1307 1237,1317 1252,1324 1265,1332 1272,1343 1307,1343 1330,1348 1346,1354 1362,1359 1379,1369 1374,1365 1345,1360 1328,1360 1371,1399 1322,1391 1283,1373 1240,1345 1201,1311 1173,1284 1151,1259 1147,1251 1146,1245 1149,1238 1154,1234 1162,1229 1172,1230 1300,1300 1310,1303 1317,1303 1321,1301 1323,1297 1325,1292 1322,1285 1314,1276 1219,1211 1208,1203 1204,1195 1203,1189 1207,1182 1214,1180 1222,1182 1296,1220 ; 1287,1078 1446,1223 1287,1078
  text "Tx-" at 570,3040 h45
  text "Tx+" at 570,2940 h45
  text "Rx-" at 570,2840 h45
  text "Rx+" at 570,2740 h45
  text "5V" at 1020,2440 h45 r90
  text "Tx-" at 570,2380 h45
  text "Iso12V" at 3010,2370 h45
  text "IsoGnd" at 1130,2340 h45 r90
  text "Iso3.3V" at 1230,2310 h45 r90
  text "Tx+" at 570,2280 h45
  text "RxCTD" at 3010,2270 h45
  text "En" at 870,2240 h45
  text "Rx-" at 570,2180 h45
  text "TxCTD" at 3010,2170 h45
  text "BusPos" at 870,2130 h45
  text "Rx+" at 570,2080 h45
  text "IsoGnd" at 3000,2070 h45
  text "Trig" at 870,2040 h45
  text "ADUM" at 230,1950 h45 r90
  text "BusGnd" at 870,1940 h45
  text "ADUM" at 200,1790 h45 r270
  text "1" at 880,1740 h45
  text "Tx-" at 570,1730 h45
  text "2" at 870,1640 h45
  text "Tx+" at 570,1630 h45
  text "3" at 870,1540 h45
  text "Rx-" at 570,1530 h45
  text "6" at 870,1440 h45
  text "Rx+" at 570,1430 h45
  text "M  B  A  R  I" at 920,1390 h55
  text "LM317" at 110,1220 h45
  text "J3" at 3150,1110 h45
  text "Tx-" at 570,1090 h45
  text "1" at 880,1080 h45
  text "6-Iso12V" at 3150,1040 h45
  text "Copyright 2004 MBARI" at 930,1000 h45
  text "Tx+" at 570,990 h45
  text "2" at 870,980 h45
  text "5,4-NC" at 3150,980 h45
  text "3-RxPSA" at 3150,920 h45
  text "EthSerialBrickR1" at 935,916.68 h45
  text "Rx-" at 570,890 h45
  text "3" at 870,880 h45
  text "2-IsoGnd" at 3150,860 h45
  text "12-February-2004" at 935,836.68 h45
  text "1-IsoTrig" at 3150,800 h45
  text "Rx+" at 570,790 h45
  text "6" at 870,780 h45
  text "Made in U.S.A." at 935,766.68 h45
  text ".GTO" at 15240,-540 h90
Bottom Overlay:
  text "Copyright 2004 MBARI" at 1630,1730 h45
  text "EthSerialBrickR1" at 1625,1646.68 h45
  text "12-February-2004" at 1625,1566.68 h45
  text "Made in U.S.A." at 1625,1496.68 h45
  text ".GBO" at 15250,-540 h90
Top Solder:
  text ".GTS" at 15250,-540 h90
Bottom Solder:
  text ".GBS" at 15250,-540 h90
Drill Guide:
  text ".GG1" at 15250,-540 h90
Mechanical 4:
  the board outline again, w10
Mechanical 16:
  lines w5: -800,1950 -600,1950 ; -800,4700 -600,4700 ; -800,7450 -600,7450 ; 2000,9600 2000,9800 ; 2035,-800 2035,-600 ; 4865,-800 4865,-600 ; 4865,9600 4865,9800 ; 7700,-800 7700,-600 ; 7700,9600 7700,9800 ; 9700,0 15600,0 ; 10530,-800 10530,-600 ; 10530,9600 10530,9800 ; 11100,-300 15600,-300 ; 11100,300 12600,300 ; 12600,-600 12600,0 12600,600 ; 13365,-800 13365,-600 ; 13365,9600 13365,9800 ; 14700,-600 14700,0 ; 15600,1950 15800,1950 ; 15600,4700 15800,4700 ; 15600,7450 15800,7450 ; 11100,-600 9700,-600 9700,600 11100,600 ; 11100,-600 15600,-600 ; 11100,-600 11100,600 ; 11100,600 12600,600 ; 12600,600 15600,600 15600,-600 ; 15600,-600 -600,-600 -600,9600 15600,9600 15600,-600 ; -800,-800 -800,9800 15800,9800 15800,-800 -800,-800
  lines w10: 10033,446 10065,444 10096,426 10197,335 10210,339 10217,338 10331,251 ; 10088,428 10191,331 ; 10196,328 10211,332 10326,244 ; 10313,228 10359,255 10418,309 10421,316 10421,326 10419,329 10413,330 10406,330 ; 10344,230 10391,193 ; 10348,237 10396,199 10548,337 10557,341 10571,336 10650,422 10653,417 10682,443 10702,447 ; 10420,315 10420,323 10418,327 10413,329 10406,330 ; 10554,333 10569,328 ; 10576,332 10641,405 ; 10644,402 10650,411 ; 10406,330 10399,327 10356,307 10339,296 10316,292 10312,297 10313,309 10351,341 10419,388 10430,404 10426,415 10420,417 10396,411 10360,391 10312,363 10282,353 10278,357 10289,372 10307,387 10329,417 10347,427 10362,434 10375,442 10382,453 10417,453 10440,458 10456,464 10472,469 10489,479 10484,475 10455,470 10438,470 10481,509 10432,501 10393,483 10350,455 10311,421 10283,394 10261,369 10257,361 10256,355 10259,348 10264,344 10272,339 10282,340 10410,410 10420,413 10427,413 10431,411 10433,407 10435,402 10432,395 10424,386 10329,321 10318,313 10314,305 10313,299 10317,292 10324,290 10332,292 10406,330 ; 10397,188 10556,333 10397,188
  text "1" at 601.34,9665 h70
  text "2" at 3427,9665 h70
  text "3" at 6252,9665 h70
  text "4" at 9093.01,9665 h70
  text "5" at 11927,9665 h70
  text "6" at 14762,9665 h70
  text "A" at -725,8822 h70
  text "A" at 15675,8822 h70
  text "B" at -725,6088.02 h70
  text "B" at 15675,6088.02 h70
  text "C" at -725,3307 h70
  text "C" at 15675,3307 h70
  text "M  B  A  R  I" at 10030,500 h55
  text "ENGINEER:" at 11150,500 h45
  text "TITLE:" at 12650,500 h45
  text "D" at -725,485 h70
  text "D" at 15675,485 h70
  text "Mark Sibenac" at 11660,470 h70
  text "Ethernet to Serial Brick" at 13000,380 h90
  text "1 831 775 2028" at 11650,330 h60
  text "PCB DESIGNER:" at 11150,205 h45
  text "Mark Sibenac" at 11680,170 h70
  text "For use with Mapping AUV" at 13020,160 h90
  text "Copyright      2004" at 9880,150 h60
  text "Monterey Bay Aquarium Research Institute" at 9750,40 h45
  text "1 831 775 2028" at 11670,30 h60
  text "DATE:" at 11150,-100 h45
  text "PART NO.:" at 12650,-100 h45
  text "REV:" at 14750,-100 h45
  text ".PRINT_DATE" at 11200,-220 h70
  text "1" at 15030,-220 h90
  text "EthSerialBrickR1" at 13010,-230 h60
  text "M.B.A.R.I." at 9780,-240 h100
  text "7700 Sandholdt Rd." at 9770,-340 h60
  text "FILE NAME:" at 11150,-400 h45
  text "DWG NO:" at 12650,-400 h45
  text "GERBER:" at 14750,-400 h45
  text "Moss Landing, CA 95039" at 9770,-450 h60
  text "1002306" at 13010,-490 h60
  text ".PCB_FILE_NAME_NO_PATH" at 11200,-520 h70
  text ".GM16" at 14860,-530 h70
  text "Fax: 1 831 775 1646" at 9770,-550 h60
  text "1" at 601.34,-735 h70
  text "2" at 3427,-735 h70
  text "3" at 6252,-735 h70
  text "4" at 9093.01,-735 h70
  text "5" at 11927,-735 h70
  text "6" at 14762,-735 h70
Drill Drawing:
  text ".LEGEND" at 9745,870 h60
  text "Drill Drawing." at 9725,780 h60
  text ".GD1" at 15245,-540 h90

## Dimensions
0,0 to 3550,0 on Mechanical 4
0,3775 to 0,0 on Mechanical 4
200,200 to 0,0 on Mechanical 4
200,200 to 0,0 on Mechanical 4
